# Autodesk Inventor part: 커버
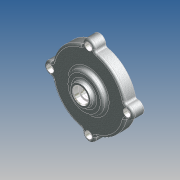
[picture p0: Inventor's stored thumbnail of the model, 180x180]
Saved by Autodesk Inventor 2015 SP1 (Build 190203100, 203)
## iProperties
Created: 2012-05
Part Number: 커버
Document SubType Name: 모델링
Designer: SeoGD™
Material: 알루미늄 6061
Appearance: 알루미늄 캐스트
Mass: 195.931 g
Surface Area: 278.607 cm^2
Volume: 72.5671 cm^3
Density: 2.7 g/cm^3
변환 표준: STEP AP214IS
파일 이름: C:\Users\SeoGD\Desktop\?쒗뿕\而ㅻ쾭-1.stp
전처리기: Build: 253, Release: 2010 SP1 - Date: Wed 07/29/2009
전송 단위: 밀리미터
불확실성: 0.01
Author: SeoGD™
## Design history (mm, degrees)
sketch "스케치1"
  geometry: L1 (0, 0)-(0, 26); L2 (50, 0)-(50, 15); L3 (50, 15)-(25, 15); L4 (25, 15)-(25, 21); L5 (25, 21)-(15, 21); L6 (15, 21)-(13.66, 26); L7 (13.66, 26)-(10, 26); L8 (50, 0)-(45, 0); L9 (45, 0)-(45, 10); L10 (45, 10)-(14.5, 10); L11 (14.5, 10)-(13.266, 3); L12 (13.266, 3)-(11, 3); L13 (11, 3)-(11, 16); L14 (11, 16)-(7.5, 16); L15 (7.5, 16)-(7.5, 19); L16 (7.5, 19)-(10, 19); L17 (10, 19)-(10, 26)
  constraints: 34 end point, 10 parallel, 2 perpendicular, 2 point on line, 1 vertical
  dimensions: "d11" = 100 diameter of L2 L1; "d12" = 22 diameter of L13 L1; "d13" = 90 diameter of L9 L1; "d14" = 15 distance between parallel lines of L3 L8; "d15" = 10 distance between parallel lines of L8 L10; "d16" = 29 diameter of L10.end L1; "d17" = 100 deg angle of L11 L10; "d18" = 7 distance between parallel lines of L12 L10; "d19" = 13 distance between parallel lines of L14 L12; "d20" = 3 distance between parallel lines of L16 L14; "d21" = 15 diameter of L15 L1; "d22" = 20 diameter of L17 L1; "d23" = 30 diameter of L5.end L1; "d24" = 6 distance between parallel lines of L5 L3; "d25" = 50 diameter of L4 L1; "d26" = 105 deg angle of L5 L6; "d50" = 26 distance of L1.start L1.end
revolve "회전1" sketch "스케치1" stored, may be unused: angle "d27" = 90 deg
sketch "스케치2" dims "d29" = 104
  geometry: A1 r 8.5 centre (0, 52) between (8.074, 49.344) and (-8.074, 49.344); A2 r 50 centre (0, 0) between (-8.074, 49.344) and (8.074, 49.344) reference; 2 further points
  constraints: 4 point on circle, 2 vertical alignment, 1 centre point, 1 coincident, 2 other
  dimensions: "d28" = 17 diameter of A1
extrude "돌출1" join sketch "스케치2" stored distance "d30" = 10; taper "d31" = 0 deg
fillet "모깎기3" dims "d32" = 3
fillet "모깎기4" dims "d45" = 3, "d46" = 0.2
chamfer "모따기1" distance "d47" = 1; stored, may be unused: second distance "d48" = 2, angle "d49" = 45 deg
hole "구멍2" diameter "d38" = 5.5; stored, may be unused: countersink angle "d42" = 90 deg, drill point angle "d44" = 118 deg; dims "d36" = 10, "d37" = 10, "d39" = 6, "d40" = 9.5, "d41" = 5.4, "d43" = 8
node "솔리드1"
node "솔리드 본체"
node "곡면 본체"
pattern_circular "원형 패턴1" dims angle "d34" = 360 deg
pattern_circular "원형 패턴2" dims angle "d52" = 360 deg
node "솔리드2"
